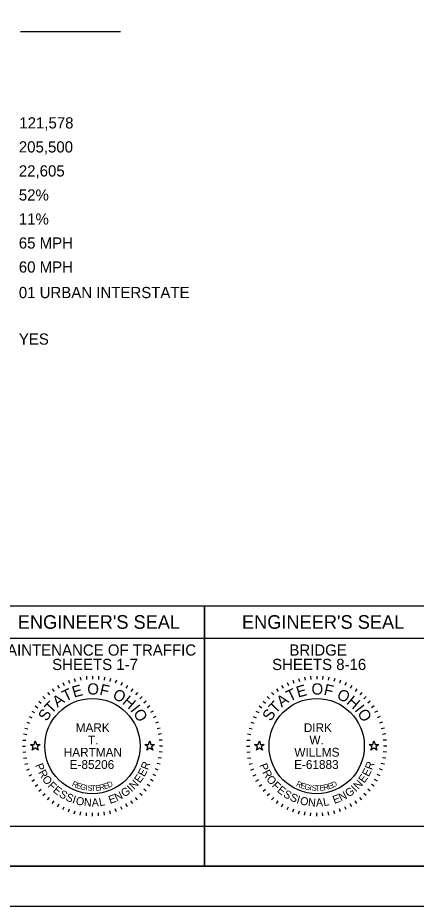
# Model space of a CAD drawing. Extents: x 0 to 34, y 0 to 22.
# Drawn here: x 7.72 to 12.69, y 0 to 11.1 of the extents above; entities that cross this region are included whole.
import ezdxf

# ---------------------------------------------------------------- set-up
doc = ezdxf.new("R2010")
doc.units = 0
for name, color, linetype in [('SH_Border', 7, 'Continuous'), ('SH_Cut_Line', 7, 'Continuous'), ('SH_Data', 7, 'Continuous'), ('SH_Seal', 7, 'Continuous'), ('SH_Text', 7, 'Continuous')]:
    doc.layers.add(name, color=color, linetype=linetype)

msp = doc.modelspace()

# ---------------------------------------------------------------- linework, layer by layer
at = {"layer": 'SH_Border'}
msp.add_lwpolyline([(1.5, 21.5), (33.5, 21.5), (33.5, 0.5), (1.5, 0.5)], close=True, dxfattribs=at)
at = {"layer": 'SH_Cut_Line'}
msp.add_lwpolyline([(0, 0), (34, 0), (34, 22), (0, 22)], close=True, dxfattribs=at)
at = {"layer": 'SH_Data'}
for p, q in [((9, 10.922), (7.75, 10.922)), ((7.251, 3.75), (10.051, 3.75)), ((10.051, 3.75), (10.051, 0.5)), ((10.051, 0.5), (10.051, 3.75)), ((10.051, 3.75), (12.851, 3.75)), ((7.251, 3.35), (10.051, 3.35)), ((10.051, 3.35), (12.851, 3.35)), ((7.251, 0.5), (10.051, 0.5)), ((10.051, 0.5), (12.851, 0.5))]:
    msp.add_line(p, q, dxfattribs=at)
for points in [[(7.251, 0.5), (7.251, 1), (10.051, 1), (10.051, 0.5)], [(10.051, 0.5), (10.051, 1), (12.851, 1), (12.851, 0.5)]]:
    msp.add_lwpolyline(points, close=True, dxfattribs=at)
at = {"layer": 'SH_Seal'}
for p, q in [((8.281, 2.793), (8.298, 2.757)), ((8.352, 2.822), (8.365, 2.785)), ((8.424, 2.845), (8.435, 2.807)), ((8.499, 2.862), (8.506, 2.822)), ((8.575, 2.872), (8.578, 2.832)), ((8.651, 2.875), (8.651, 2.835)), ((8.727, 2.872), (8.724, 2.832)), ((8.803, 2.862), (8.796, 2.822)), ((8.877, 2.845), (8.867, 2.807)), ((8.95, 2.822), (8.936, 2.785)), ((9.021, 2.793), (9.004, 2.757)), ((11.081, 2.793), (11.098, 2.757)), ((11.152, 2.822), (11.165, 2.785)), ((11.224, 2.845), (11.235, 2.807)), ((11.299, 2.862), (11.306, 2.822)), ((11.375, 2.872), (11.378, 2.832)), ((11.451, 2.875), (11.451, 2.835)), ((11.527, 2.872), (11.524, 2.832)), ((11.603, 2.862), (11.596, 2.822)), ((11.677, 2.845), (11.667, 2.807)), ((11.75, 2.822), (11.736, 2.785)), ((11.821, 2.793), (11.804, 2.757)), ((8.088, 2.67), (8.114, 2.64)), ((8.149, 2.717), (8.172, 2.684)), ((8.213, 2.758), (8.233, 2.723)), ((9.088, 2.758), (9.068, 2.723)), ((9.153, 2.717), (9.13, 2.684)), ((9.213, 2.67), (9.188, 2.64)), ((10.888, 2.67), (10.914, 2.64)), ((10.949, 2.717), (10.972, 2.684)), ((11.013, 2.758), (11.033, 2.723)), ((11.888, 2.758), (11.868, 2.723)), ((11.953, 2.717), (11.93, 2.684)), ((12.013, 2.67), (11.988, 2.64)), ((7.981, 2.562), (8.011, 2.537)), ((8.032, 2.619), (8.06, 2.59)), ((9.27, 2.619), (9.241, 2.59)), ((9.321, 2.562), (9.291, 2.537)), ((10.781, 2.562), (10.811, 2.537)), ((10.832, 2.619), (10.86, 2.59)), ((12.07, 2.619), (12.041, 2.59)), ((12.121, 2.562), (12.091, 2.537)), ((7.934, 2.502), (7.967, 2.479)), ((9.368, 2.502), (9.335, 2.479)), ((10.734, 2.502), (10.767, 2.479)), ((12.168, 2.502), (12.135, 2.479)), ((7.858, 2.37), (7.894, 2.353)), ((7.893, 2.438), (7.928, 2.418)), ((9.409, 2.438), (9.374, 2.418)), ((9.444, 2.37), (9.408, 2.353)), ((10.658, 2.37), (10.694, 2.353)), ((10.693, 2.438), (10.728, 2.418)), ((12.209, 2.438), (12.174, 2.418)), ((12.244, 2.37), (12.208, 2.353)), ((7.806, 2.226), (7.844, 2.216)), ((7.829, 2.299), (7.866, 2.286)), ((9.473, 2.299), (9.436, 2.286)), ((9.496, 2.226), (9.457, 2.216)), ((10.606, 2.226), (10.644, 2.216)), ((10.629, 2.299), (10.666, 2.286)), ((12.273, 2.299), (12.236, 2.286)), ((12.296, 2.226), (12.257, 2.216)), ((7.789, 2.152), (7.829, 2.145)), ((9.513, 2.152), (9.473, 2.145)), ((10.589, 2.152), (10.629, 2.145)), ((12.313, 2.152), (12.273, 2.145)), ((7.776, 2), (7.816, 2)), ((7.779, 2.076), (7.819, 2.073)), ((9.523, 2.076), (9.483, 2.073)), ((9.526, 2), (9.486, 2)), ((10.576, 2), (10.616, 2)), ((10.579, 2.076), (10.619, 2.073)), ((12.323, 2.076), (12.283, 2.073)), ((12.326, 2), (12.286, 2)), ((7.779, 1.924), (7.819, 1.927)), ((9.523, 1.924), (9.483, 1.927)), ((10.579, 1.924), (10.619, 1.927)), ((12.323, 1.924), (12.283, 1.927)), ((7.789, 1.848), (7.829, 1.855)), ((7.806, 1.774), (7.844, 1.784)), ((9.496, 1.774), (9.457, 1.784)), ((9.513, 1.848), (9.473, 1.855)), ((10.589, 1.848), (10.629, 1.855)), ((10.606, 1.774), (10.644, 1.784)), ((12.296, 1.774), (12.257, 1.784)), ((12.313, 1.848), (12.273, 1.855)), ((7.829, 1.701), (7.866, 1.714)), ((9.473, 1.701), (9.436, 1.714)), ((10.629, 1.701), (10.666, 1.714)), ((12.273, 1.701), (12.236, 1.714)), ((7.858, 1.63), (7.894, 1.647)), ((7.893, 1.563), (7.928, 1.583)), ((9.409, 1.563), (9.374, 1.583)), ((9.444, 1.63), (9.408, 1.647)), ((10.658, 1.63), (10.694, 1.647)), ((10.693, 1.563), (10.728, 1.583)), ((12.209, 1.563), (12.174, 1.583)), ((12.244, 1.63), (12.208, 1.647)), ((7.934, 1.498), (7.967, 1.521)), ((7.981, 1.438), (8.011, 1.463)), ((9.321, 1.438), (9.291, 1.463)), ((9.368, 1.498), (9.335, 1.521)), ((10.734, 1.498), (10.767, 1.521)), ((10.781, 1.438), (10.811, 1.463)), ((12.121, 1.438), (12.091, 1.463)), ((12.168, 1.498), (12.135, 1.521)), ((8.032, 1.381), (8.06, 1.41)), ((8.088, 1.33), (8.114, 1.36)), ((9.213, 1.33), (9.188, 1.36)), ((9.27, 1.381), (9.241, 1.41)), ((10.832, 1.381), (10.86, 1.41)), ((10.888, 1.33), (10.914, 1.36)), ((12.013, 1.33), (11.988, 1.36)), ((12.07, 1.381), (12.041, 1.41)), ((8.149, 1.283), (8.172, 1.316)), ((8.213, 1.242), (8.233, 1.277)), ((8.281, 1.207), (8.298, 1.243)), ((9.021, 1.207), (9.004, 1.243)), ((9.088, 1.242), (9.068, 1.277)), ((9.153, 1.283), (9.13, 1.316)), ((10.949, 1.283), (10.972, 1.316)), ((11.013, 1.242), (11.033, 1.277)), ((11.081, 1.207), (11.098, 1.243)), ((11.821, 1.207), (11.804, 1.243)), ((11.888, 1.242), (11.868, 1.277)), ((11.953, 1.283), (11.93, 1.316)), ((8.352, 1.178), (8.365, 1.215)), ((8.424, 1.155), (8.435, 1.193)), ((8.499, 1.138), (8.506, 1.178)), ((8.575, 1.128), (8.578, 1.168)), ((8.651, 1.125), (8.651, 1.165)), ((8.727, 1.128), (8.724, 1.168)), ((8.803, 1.138), (8.796, 1.178)), ((8.877, 1.155), (8.867, 1.193)), ((8.95, 1.178), (8.936, 1.215)), ((11.152, 1.178), (11.165, 1.215)), ((11.224, 1.155), (11.235, 1.193)), ((11.299, 1.138), (11.306, 1.178)), ((11.375, 1.128), (11.378, 1.168)), ((11.451, 1.125), (11.451, 1.165)), ((11.527, 1.128), (11.524, 1.168)), ((11.603, 1.138), (11.596, 1.178)), ((11.677, 1.155), (11.667, 1.193)), ((11.75, 1.178), (11.736, 1.215))]:
    msp.add_line(p, q, dxfattribs=at)
for points in [[(7.875, 2.02), (7.921, 2.02), (7.936, 2.065), (7.95, 2.02), (7.997, 2.02), (7.959, 1.992), (7.974, 1.948), (7.936, 1.975), (7.898, 1.948), (7.912, 1.992)], [(9.305, 2.02), (9.351, 2.02), (9.366, 2.065), (9.38, 2.02), (9.427, 2.02), (9.389, 1.992), (9.404, 1.948), (9.366, 1.975), (9.328, 1.948), (9.342, 1.992)], [(10.675, 2.02), (10.721, 2.02), (10.736, 2.065), (10.75, 2.02), (10.797, 2.02), (10.759, 1.992), (10.774, 1.948), (10.736, 1.975), (10.698, 1.948), (10.712, 1.992)], [(12.105, 2.02), (12.151, 2.02), (12.166, 2.065), (12.18, 2.02), (12.227, 2.02), (12.189, 1.992), (12.204, 1.948), (12.166, 1.975), (12.128, 1.948), (12.142, 1.992)]]:
    msp.add_lwpolyline(points, close=True, dxfattribs=at)
for centre in [(8.651, 2), (11.451, 2)]:
    msp.add_circle(centre, 0.595, dxfattribs=at)

# ---------------------------------------------------------------- texts
at = {"layer": 'SH_Data'}
for s, height, p in [("ENGINEER'S SEAL", 0.17, (7.718, 3.465)), ("ENGINEER'S SEAL", 0.17, (10.518, 3.465)), ('MAINTENANCE OF TRAFFIC', 0.14, (7.428, 3.13)), ('BRIDGE', 0.14, (11.11, 3.13)), ('SHEETS 1-7', 0.14, (8.147, 2.95)), ('SHEETS 8-16', 0.14, (10.894, 2.95))]:
    msp.add_text(s, height=height, dxfattribs=at).set_placement(p)
at = {"layer": 'SH_Seal'}
for s, height, rotation, p in [('O', 0.14, 359.7812, (8.586, 2.644)), ('F', 0.14, 347.4362, (8.732, 2.642)), ('O', 0.14, 359.7812, (11.386, 2.644)), ('F', 0.14, 347.4362, (11.532, 2.642)), ('T', 0.14, 25.7167, (8.313, 2.552)), ('E', 0.14, 15.7571, (8.419, 2.604)), ('O', 0.14, 332.2586, (8.891, 2.602)), ('T', 0.14, 25.7167, (11.113, 2.552)), ('E', 0.14, 15.7571, (11.219, 2.604)), ('O', 0.14, 332.2586, (11.691, 2.602)), ('T', 0.14, 46.4344, (8.139, 2.396)), ('A', 0.14, 36.4747, (8.214, 2.478)), ('H', 0.14, 319.9136, (9.014, 2.536)), ('T', 0.14, 46.4344, (10.939, 2.396)), ('A', 0.14, 36.4747, (11.014, 2.478)), ('H', 0.14, 319.9136, (11.814, 2.536)), ('S', 0.14, 57.1924, (8.079, 2.301)), ('I', 0.14, 308.367, (9.117, 2.448)), ('O', 0.14, 303.1491, (9.153, 2.409)), ('S', 0.14, 57.1924, (10.879, 2.301)), ('I', 0.14, 308.367, (11.917, 2.448)), ('O', 0.14, 303.1491, (11.953, 2.409)), ('P', 0.1, 291.494, (7.933, 1.762)), ('R', 0.1, 69.2322, (9.343, 1.695)), ('P', 0.1, 291.494, (10.733, 1.762)), ('R', 0.1, 69.2322, (12.143, 1.695)), ('R', 0.1, 298.7311, (7.97, 1.672)), ('E', 0.1, 61.9951, (9.299, 1.61)), ('R', 0.1, 298.7311, (10.77, 1.672)), ('E', 0.1, 61.9951, (12.099, 1.61)), ('O', 0.1, 306.4666, (8.016, 1.588)), ('F', 0.1, 314.7068, (8.085, 1.498)), ('R', 0.07, 334.487, (8.388, 1.505)), ('D', 0.07, 23.3052, (8.852, 1.477)), ('N', 0.1, 47.0224, (9.171, 1.451)), ('E', 0.1, 54.758, (9.244, 1.531)), ('O', 0.1, 306.4666, (10.816, 1.588)), ('F', 0.1, 314.7068, (10.885, 1.498)), ('R', 0.07, 334.487, (11.188, 1.505)), ('D', 0.07, 23.3052, (11.652, 1.477)), ('N', 0.1, 47.0224, (11.971, 1.451)), ('E', 0.1, 54.758, (12.044, 1.531)), ('E', 0.1, 321.4393, (8.149, 1.435)), ('S', 0.1, 328.6764, (8.225, 1.375)), ('E', 0.07, 341.04, (8.442, 1.48)), ('G', 0.07, 347.4752, (8.492, 1.462)), ('I', 0.07, 353.7858, (8.56, 1.447)), ('S', 0.07, 356.8926, (8.587, 1.443)), ('T', 0.07, 3.0061, (8.637, 1.439)), ('E', 0.07, 6.0117, (8.69, 1.441)), ('R', 0.07, 11.9184, (8.743, 1.447)), ('E', 0.07, 17.6836, (8.801, 1.46)), ('G', 0.1, 35.0469, (9.049, 1.357)), ('I', 0.1, 43.287, (9.138, 1.421)), ('E', 0.1, 321.4393, (10.949, 1.435)), ('S', 0.1, 328.6764, (11.025, 1.375)), ('E', 0.07, 341.04, (11.242, 1.48)), ('G', 0.07, 347.4752, (11.292, 1.462)), ('I', 0.07, 353.7858, (11.36, 1.447)), ('S', 0.07, 356.8926, (11.387, 1.443)), ('T', 0.07, 3.0061, (11.437, 1.439)), ('E', 0.07, 6.0117, (11.49, 1.441)), ('R', 0.07, 11.9184, (11.543, 1.447)), ('E', 0.07, 17.6836, (11.601, 1.46)), ('G', 0.1, 35.0469, (11.849, 1.357)), ('I', 0.1, 43.287, (11.938, 1.421)), ('S', 0.1, 335.9134, (8.307, 1.327)), ('I', 0.1, 343.1505, (8.392, 1.29)), ('O', 0.1, 346.8859, (8.435, 1.275)), ('N', 0.1, 355.1261, (8.54, 1.252)), ('A', 0.1, 2.8617, (8.643, 1.244)), ('L', 0.1, 10.0987, (8.74, 1.249)), ('E', 0.1, 20.0742, (8.872, 1.277)), ('N', 0.1, 27.3113, (8.955, 1.308)), ('S', 0.1, 335.9134, (11.107, 1.327)), ('I', 0.1, 343.1505, (11.192, 1.29)), ('O', 0.1, 346.8859, (11.235, 1.275)), ('N', 0.1, 355.1261, (11.34, 1.252)), ('A', 0.1, 2.8617, (11.443, 1.244)), ('L', 0.1, 10.0987, (11.54, 1.249)), ('E', 0.1, 20.0742, (11.672, 1.277)), ('N', 0.1, 27.3113, (11.755, 1.308))]:
    msp.add_text(s, height=height, rotation=rotation, dxfattribs=at).set_placement(p)
for s, p in [('MARK', (8.441, 2.175)), ('DIRK', (11.29, 2.175)), ('T.', (8.595, 2.022)), ('W.', (11.36, 2.022)), ('HARTMAN', (8.292, 1.868)), ('WILLMS', (11.172, 1.868)), ('E-85206', (8.366, 1.715)), ('E-61883', (11.169, 1.715))]:
    msp.add_text(s, height=0.11, dxfattribs=at).set_placement(p)
at = {"layer": 'SH_Text'}
for s, p in [('121,578', (7.737, 9.714)), ('205,500', (7.731, 9.414)), ('22,605', (7.731, 9.114)), ('52%', (7.731, 8.814)), ('11%', (7.731, 8.514)), ('65 MPH', (7.731, 8.214)), ('60 MPH', (7.731, 7.914)), ('01 URBAN INTERSTATE', (7.731, 7.595)), ('YES', (7.731, 7.014))]:
    msp.add_text(s, height=0.14, dxfattribs=at).set_placement(p)

doc.saveas('drawing.dxf')
